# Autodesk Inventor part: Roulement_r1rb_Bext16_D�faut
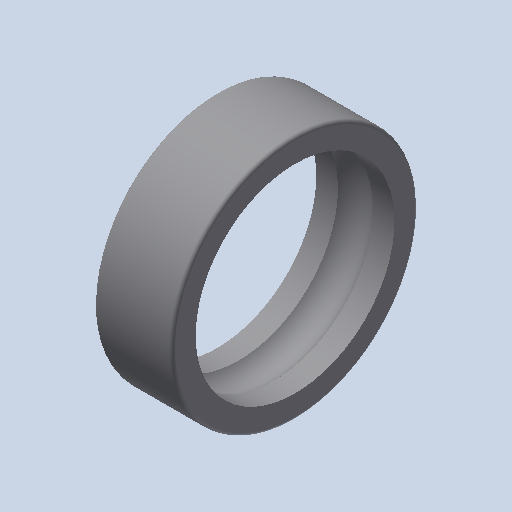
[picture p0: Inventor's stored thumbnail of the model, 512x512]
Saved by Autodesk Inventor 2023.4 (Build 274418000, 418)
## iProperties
Created: 2011-01
Part Number: Roulement_r1rb_Bext16_D�faut
Document SubType Name: Modeling
Designer: eric
Density: 1 g/cm^3
Mass: 0.82877 g
Surface Area: 11.5266 cm^2
Volume: 0.82877 cm^3
Material: Générique
Appearance: Par défaut
Author: eric
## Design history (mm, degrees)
feature "Base1"
node "Corps solides"
node "Corps surfaciques"
node "Solide1"
